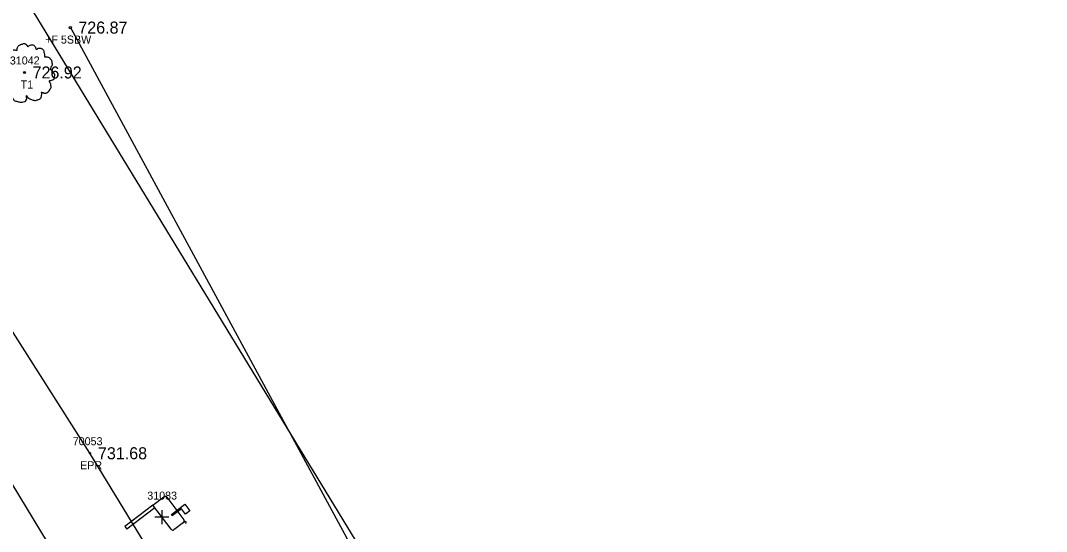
# Model space of a CAD drawing. Extents: x 1375131 to 1378678, y 999028 to 1004053.
# Drawn here: x 1377739.9 to 1377868.1, y 1001039.4 to 1001103.2 of the extents above; entities that cross this region are included whole.
import ezdxf

# ---------------------------------------------------------------- set-up
doc = ezdxf.new("R2010")
doc.units = 0
for name, color, linetype in [('Default', 7, 'Continuous'), ('RD_EX_BldgApp', 7, 'Continuous'), ('RD_EX_Fence_Other', 7, 'Continuous'), ('RD_EX_Fence_Other_txCode', 7, 'Continuous'), ('RD_EX_Road', 7, 'Continuous'), ('RD_EX_Road_txCode', 7, 'Continuous'), ('RD_EX_RW', 7, 'Continuous'), ('RD_EX_TX_Fence_Other_ELEV', 7, 'Continuous'), ('RD_EX_TX_Road_ELEV', 7, 'Continuous'), ('RD_EX_TX_VEG_ELEV', 7, 'Continuous'), ('RD_EX_VEG', 7, 'Continuous'), ('RD_EX_VEG_txCode', 7, 'Continuous'), ('RD_HC_Cl', 7, 'Continuous'), ('RD_SMD_Locator', 7, 'Continuous')]:
    doc.layers.add(name, color=color, linetype=linetype)

msp = doc.modelspace()

# ---------------------------------------------------------------- linework, layer by layer
at = {"layer": 'Default'}
for p, q in [((1377757.62, 1001042.09), (1377757.62, 1001040.34)), ((1377758.49, 1001041.22), (1377756.74, 1001041.22))]:
    msp.add_line(p, q, dxfattribs=at)
at = {"layer": 'RD_EX_BldgApp'}
for p, q in [((1377756.48, 1001042.73), (1377757.87, 1001043.78)), ((1377758.22, 1001043.73), (1377760.35, 1001040.91)), ((1377756.48, 1001042.73), (1377752.96, 1001040.07)), ((1377756.73, 1001042.39), (1377753.21, 1001039.73)), ((1377758.76, 1001039.71), (1377756.48, 1001042.73)), ((1377758.79, 1001041.56), (1377760.46, 1001042.83)), ((1377760.04, 1001042.27), (1377758.9, 1001041.41)), ((1377760.54, 1001041.6), (1377760.04, 1001042.27)), ((1377760.46, 1001042.83), (1377761.08, 1001042.01)), ((1377761.08, 1001042.01), (1377760.54, 1001041.6)), ((1377758.9, 1001041.41), (1377758.79, 1001041.56)), ((1377760.31, 1001040.56), (1377759.11, 1001039.66)), ((1377760.31, 1001040.56), (1377760.51, 1001040.71)), ((1377760.51, 1001040.71), (1377760.66, 1001040.51)), ((1377760.66, 1001040.51), (1377760.56, 1001040.44)), ((1377752.96, 1001040.07), (1377753.21, 1001039.73))]:
    msp.add_line(p, q, dxfattribs=at)
for centre, start, end in [((1377758.03, 1001043.58), 37.0668, 127.0668), ((1377760.15, 1001040.76), 307.0668, 37.0668), ((1377758.96, 1001039.86), 217.0668, 307.0668)]:
    msp.add_arc(centre, 0.25, start, end, dxfattribs=at)
at = {"layer": 'RD_EX_Fence_Other'}
msp.add_line((1377746.17, 1001102.37), (1377808.24, 1000987.87), dxfattribs=at)
at = {"layer": 'RD_EX_Road'}
msp.add_lwpolyline([(1377899.67, 1000800.29), (1377898.72, 1000801.84), (1377870.31, 1000849.94), (1377847.28, 1000887.89), (1377815.15, 1000940.58), (1377781.51, 1000995.26), (1377748.62, 1001049.21), (1377716.58, 1001099.53), (1377686.67, 1001148.78), (1377656.47, 1001199.11), (1377629.54, 1001244.18), (1377599.89, 1001292.67), (1377570.87, 1001341.43), (1377539.83, 1001392.47), (1377511.01, 1001440.31), (1377480.72, 1001490), (1377449.73, 1001541.49), (1377420.9, 1001591.95), (1377390.45, 1001644.41)], dxfattribs=at)
at = {"layer": 'RD_EX_RW'}
msp.add_line((1377592.75, 1001348.44), (1377983.57, 1000707.36), dxfattribs=at)
at = {"layer": 'RD_EX_VEG'}
for centre, radius in [((1377740.45, 1001096.76), 0.125), ((1377740.44, 1001096.75), 0.00005)]:
    msp.add_circle(centre, radius, dxfattribs=at)
for points in [[(1377740.51, 1001100.34), (1377740.36, 1001100.35), (1377740.2, 1001100.3), (1377740.07, 1001100.25), (1377739.96, 1001100.22), (1377739.85, 1001100.17), (1377739.7, 1001100.08), (1377739.59, 1001099.98), (1377739.52, 1001099.85), (1377739.5, 1001099.74), (1377739.47, 1001099.6), (1377739.47, 1001099.52), (1377739.41, 1001099.5), (1377739.34, 1001099.52), (1377739.21, 1001099.55), (1377739.09, 1001099.55), (1377738.96, 1001099.55), (1377738.79, 1001099.54), (1377738.61, 1001099.54), (1377738.47, 1001099.52), (1377738.31, 1001099.49), (1377738.12, 1001099.43), (1377737.95, 1001099.37), (1377737.8, 1001099.24), (1377737.67, 1001099), (1377737.61, 1001098.83), (1377737.54, 1001098.7), (1377737.61, 1001098.48), (1377737.7, 1001098.3), (1377737.71, 1001098.2), (1377737.75, 1001097.99), (1377737.8, 1001097.88), (1377737.86, 1001097.78), (1377737.82, 1001097.77), (1377737.64, 1001097.74), (1377737.49, 1001097.69), (1377737.27, 1001097.58), (1377737.16, 1001097.47), (1377737.11, 1001097.3), (1377737.1, 1001097.13), (1377737.05, 1001097.03), (1377737.01, 1001096.89), (1377737, 1001096.85), (1377736.98, 1001096.69), (1377737.03, 1001096.47), (1377737.04, 1001096.29), (1377737.1, 1001096.18), (1377737.17, 1001096.09), (1377737.26, 1001095.97), (1377737.46, 1001095.86), (1377737.62, 1001095.81), (1377737.72, 1001095.79), (1377737.64, 1001095.54), (1377737.61, 1001095.37), (1377737.55, 1001095.17), (1377737.55, 1001095.13), (1377737.52, 1001094.89), (1377737.6, 1001094.73), (1377737.64, 1001094.54), (1377737.72, 1001094.43), (1377737.86, 1001094.28), (1377738.02, 1001094.17), (1377738.27, 1001094.11), (1377738.47, 1001094.12), (1377738.76, 1001094.21), (1377738.89, 1001094.24), (1377738.87, 1001094.16), (1377738.89, 1001093.97), (1377738.89, 1001093.76), (1377738.96, 1001093.59), (1377739.01, 1001093.46), (1377739.09, 1001093.33), (1377739.25, 1001093.22), (1377739.45, 1001093.18), (1377739.66, 1001093.11), (1377739.89, 1001093.07), (1377740.14, 1001093.06), (1377740.44, 1001093.13), (1377740.57, 1001093.19), (1377740.62, 1001093.28), (1377740.72, 1001093.47), (1377740.7, 1001093.58), (1377740.71, 1001093.88), (1377740.76, 1001093.79), (1377740.85, 1001093.62), (1377741.1, 1001093.47), (1377741.3, 1001093.38), (1377741.54, 1001093.31), (1377741.69, 1001093.27), (1377741.92, 1001093.31), (1377742.11, 1001093.34), (1377742.3, 1001093.41), (1377742.45, 1001093.54), (1377742.54, 1001093.68), (1377742.56, 1001093.82), (1377742.6, 1001094.01), (1377742.62, 1001094.09)], [(1377742.62, 1001094.09), (1377742.59, 1001094.18), (1377742.56, 1001094.31), (1377742.6, 1001094.29), (1377742.69, 1001094.27), (1377742.82, 1001094.21), (1377742.93, 1001094.17), (1377743.1, 1001094.18), (1377743.23, 1001094.23), (1377743.46, 1001094.37), (1377743.6, 1001094.61), (1377743.73, 1001094.81), (1377743.77, 1001094.97), (1377743.75, 1001095.08), (1377743.73, 1001095.33), (1377743.63, 1001095.46), (1377743.61, 1001095.52), (1377743.56, 1001095.72), (1377743.6, 1001095.74), (1377743.73, 1001095.77), (1377743.92, 1001095.83), (1377744.06, 1001095.89), (1377744.17, 1001095.98), (1377744.21, 1001096.09), (1377744.2, 1001096.29), (1377744.22, 1001096.49), (1377744.18, 1001096.57), (1377744.13, 1001096.64), (1377744.1, 1001096.74), (1377744.02, 1001096.82), (1377743.97, 1001096.89), (1377743.92, 1001096.94), (1377743.86, 1001097.02), (1377743.77, 1001097.08), (1377743.7, 1001097.1), (1377743.67, 1001097.18), (1377743.75, 1001097.28), (1377743.77, 1001097.33), (1377743.78, 1001097.44), (1377743.9, 1001097.62), (1377743.92, 1001097.82), (1377743.9, 1001098.03), (1377743.87, 1001098.17), (1377743.8, 1001098.3), (1377743.7, 1001098.43), (1377743.63, 1001098.52), (1377743.55, 1001098.58), (1377743.38, 1001098.64), (1377743.26, 1001098.67), (1377743.08, 1001098.67), (1377742.98, 1001098.69), (1377743, 1001098.72), (1377743, 1001098.79), (1377743, 1001098.93), (1377742.96, 1001099.15), (1377742.88, 1001099.4), (1377742.88, 1001099.42), (1377742.83, 1001099.54), (1377742.72, 1001099.64), (1377742.64, 1001099.69), (1377742.54, 1001099.75), (1377742.41, 1001099.77), (1377742.26, 1001099.77), (1377742.12, 1001099.74), (1377742.02, 1001099.69), (1377741.94, 1001099.63), (1377741.9, 1001099.7), (1377741.85, 1001099.85), (1377741.82, 1001099.93), (1377741.75, 1001100.02), (1377741.64, 1001100.12), (1377741.41, 1001100.18), (1377741.1, 1001100.14), (1377740.95, 1001100.04), (1377740.87, 1001099.95), (1377740.85, 1001100.02), (1377740.75, 1001100.12), (1377740.7, 1001100.2), (1377740.61, 1001100.27), (1377740.54, 1001100.32), (1377740.49, 1001100.34)]]:
    msp.add_spline(points, degree=3, dxfattribs=at)
at = {"layer": 'RD_HC_Cl'}
msp.add_line((1377564.57, 1001331.26), (1377955.4, 1000690.18), dxfattribs=at)
at = {"layer": 'RD_SMD_Locator'}
for centre, radius in [((1377746.17, 1001102.37), 0.15), ((1377740.45, 1001096.76), 0.075), ((1377748.62, 1001049.21), 0.075)]:
    msp.add_circle(centre, radius, dxfattribs=at)

# ---------------------------------------------------------------- texts
at = {"layer": 'Default'}
msp.add_text('31083', height=1, dxfattribs=at).set_placement((1377755.78, 1001043.42))
at = {"layer": 'RD_EX_Fence_Other_txCode'}
msp.add_text('+F 5SBW', height=1, dxfattribs=at).set_placement((1377743.02, 1001100.37))
at = {"layer": 'RD_EX_Road_txCode'}
for s, p in [('70053', (1377746.47, 1001050.21)), ('EPR', (1377747.39, 1001047.21))]:
    msp.add_text(s, height=1, dxfattribs=at).set_placement(p)
at = {"layer": 'RD_EX_TX_Fence_Other_ELEV'}
msp.add_text('726.87', height=1.5, dxfattribs=at).set_placement((1377747.17, 1001101.62))
at = {"layer": 'RD_EX_TX_Road_ELEV'}
msp.add_text('731.68', height=1.5, dxfattribs=at).set_placement((1377749.62, 1001048.46))
at = {"layer": 'RD_EX_TX_VEG_ELEV'}
msp.add_text('726.92', height=1.5, dxfattribs=at).set_placement((1377741.45, 1001096.01))
at = {"layer": 'RD_EX_VEG_txCode'}
for s, p in [('31042', (1377738.61, 1001097.76)), ('T1', (1377739.96, 1001094.76))]:
    msp.add_text(s, height=1, dxfattribs=at).set_placement(p)

doc.saveas('drawing.dxf')
